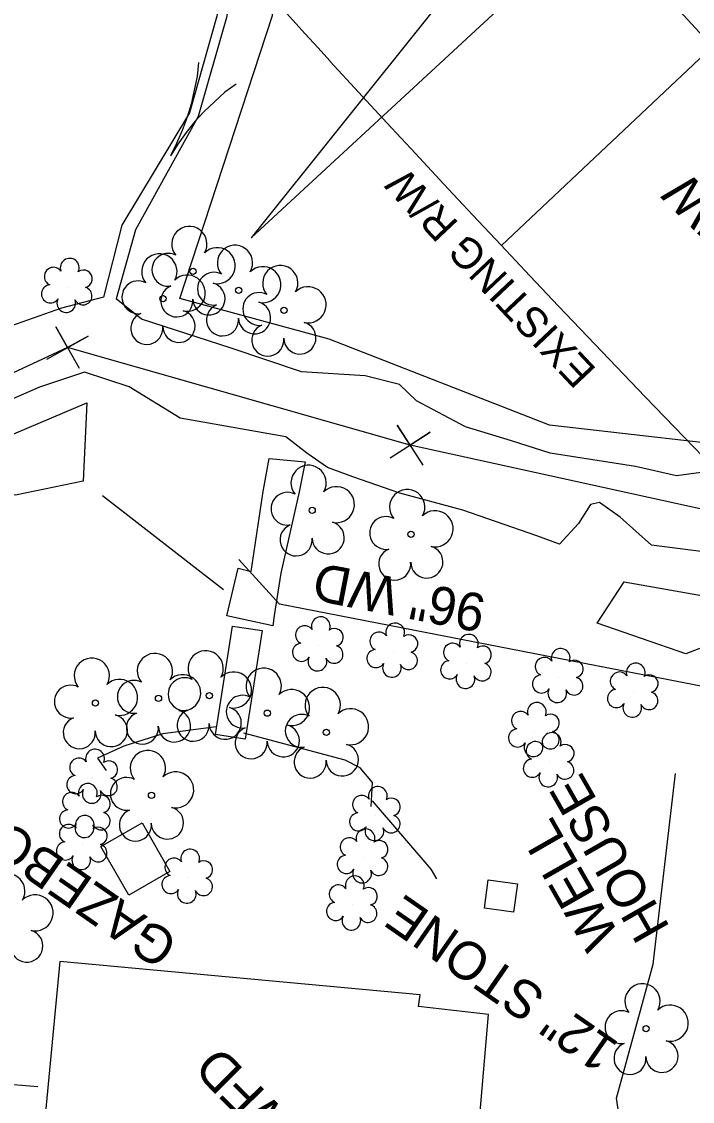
# Model space of a CAD drawing. Extents: x 472260 to 482161, y 489063 to 507124.
# Drawn here: x 478879.6 to 478950.3, y 493938.2 to 494051.9 of the extents above; entities that cross this region are included whole.
import ezdxf

# ---------------------------------------------------------------- set-up
doc = ezdxf.new("R2010")
doc.units = 0
for name, color, linetype in [('Exist Plan Preparation Watershed Blue', 7, 'Continuous'), ('Exist Roads EOP Other Cogo Point CELL', 7, 'Continuous'), ('Exist Structure Minor Drop Inlet Cogo Elevation', 7, 'Continuous'), ('Exist Structure Minor Drop Inlet Cogo Number', 7, 'Continuous'), ('Exist Structure Minor Pipes CMP 15 Inch Cogo Comment', 7, 'Continuous'), ('Exist Structure Minor Pipes CMP 15 Inch Cogo Elevation', 7, 'Continuous'), ('Exist Structure Minor Pipes CMP 15 Inch Cogo Point CELL', 7, 'Continuous'), ('Exist Structure Minor Pipes CMP 30 Inch', 7, 'Continuous'), ('Exist Utilities Water Meter CELL', 7, 'Continuous'), ('Prop Drainage Structure Drop Inlet Grate 2 Narrow Slots and Flat Grates 840 29 CELL', 7, 'Continuous'), ('Prop Drainage Structure Drop Inlet Grate 2 Wide Slots and Flat Grates 840 20 Label', 7, 'Continuous'), ('Prop Drainage Structure Outlet Berm Ditch 850 10 CELL', 7, 'Continuous'), ('Prop Drainage Structure Outlet Berm Ditch 850 10 Label', 7, 'Continuous'), ('Prop Drainage Structure Pipe RCP 24in Class III', 7, 'Continuous'), ('Prop Drainage Structure Pipe RCP 72in Class III', 7, 'Continuous'), ('Prop Drainage Structure Pipe Side Drain 18in Label', 7, 'Continuous'), ('Prop Drainage Structure Tops and Inverts LABEL', 7, 'Continuous'), ('Prop Erosion Rip Rap Pad at Outlet CELL', 7, 'Continuous'), ('Prop SS Fill Line', 7, 'Continuous'), ('Scratch_Level_7', 7, 'Continuous'), ('Scratch_Level_8', 7, 'Continuous')]:
    doc.layers.add(name, color=color, linetype=linetype)

msp = doc.modelspace()

# ---------------------------------------------------------------- linework, layer by layer
at = {"layer": 'Exist Plan Preparation Watershed Blue'}
msp.add_lwpolyline([(478901.24, 493989.35), (478902.43, 493994.36), (478903.79, 493994), (478905.06, 494002.44), (478905.69, 494005.92), (478909.5, 494005.56), (478908.87, 494002.4), (478906.92, 493993.82), (478906.21, 493989.37), (478906.07, 493988.3), (478901.24, 493989.35)], dxfattribs=at)
msp.add_lwpolyline([(478904.96, 493987.8), (478903.16, 493976.36), (478900.03, 493976.83), (478901.83, 493988.27)], close=True, dxfattribs=at)
at = {"layer": 'Exist Roads EOP Other Cogo Point CELL'}
for p, q in [((478884.44, 494017.59), (478884.44, 494017.59)), ((478920.54, 494007.33), (478920.54, 494007.33))]:
    msp.add_line(p, q, dxfattribs=at)
for points in [[(478882.25, 494016.37), (478886.62, 494018.81), (478884.44, 494017.59), (478883.22, 494019.77), (478885.65, 494015.41)], [(478918.44, 494005.98), (478922.65, 494008.67), (478920.54, 494007.33), (478919.2, 494009.43), (478921.89, 494005.22)]]:
    msp.add_lwpolyline(points, dxfattribs=at)
at = {"layer": 'Exist Structure Minor Drop Inlet Cogo Elevation'}
for centre, radius, start, end in [((480724.65, 495711.31), 2460.21, 219.63873, 222.54643), ((480415.92, 495427.95), 2041.17, 222.54643, 230.46528)]:
    msp.add_arc(centre, radius, start, end, dxfattribs=at)
at = {"layer": 'Exist Structure Minor Drop Inlet Cogo Number'}
for p, q in [((478884.44, 494017.59), (478874.79, 494013.14)), ((478920.54, 494007.33), (478884.44, 494017.59)), ((478958.36, 493999.01), (478920.54, 494007.33))]:
    msp.add_line(p, q, dxfattribs=at)
at = {"layer": 'Exist Structure Minor Pipes CMP 15 Inch Cogo Comment'}
msp.add_line((478930.18, 494028.34), (478966.81, 494062.85), dxfattribs=at)
at = {"layer": 'Exist Structure Minor Pipes CMP 15 Inch Cogo Elevation'}
msp.add_lwpolyline([(478922.85, 494052.91), (478903.78, 494029.16), (479097.91, 494208.4), (479078.84, 494184.65)], dxfattribs=at)
at = {"layer": 'Exist Utilities Water Meter CELL'}
msp.add_lwpolyline([(478944.73, 493922.51), (478942.31, 493938.56), (478946.19, 493952.67), (478948.54, 493972.74)], dxfattribs=at)
at = {"layer": 'Prop Drainage Structure Drop Inlet Grate 2 Narrow Slots and Flat Grates 840 29 CELL'}
msp.add_lwpolyline([(478916.56, 493969.87), (478922.73, 493962.68), (478923.32, 493961.64)], dxfattribs=at)
at = {"layer": 'Prop Drainage Structure Drop Inlet Grate 2 Wide Slots and Flat Grates 840 20 Label'}
for p, q in [((478897.67, 494025.63), (478897.67, 494025.63)), ((478902.48, 494023.63), (478902.48, 494023.63)), ((478894.51, 494022.74), (478894.51, 494022.74)), ((478907.25, 494021.51), (478907.25, 494021.51)), ((478910.23, 494000.46), (478910.23, 494000.46)), ((478920.64, 493997.92), (478920.64, 493997.92)), ((478887.38, 493980.16), (478887.38, 493980.16)), ((478894.03, 493980.65), (478894.03, 493980.65)), ((478899.39, 493980.94), (478899.39, 493980.94)), ((478905.51, 493979.09), (478905.51, 493979.09)), ((478911.73, 493977.07), (478911.73, 493977.07)), ((478893.29, 493970.43), (478893.29, 493970.43)), ((478945.43, 493945.86), (478945.43, 493945.86))]:
    msp.add_line(p, q, dxfattribs=at)
for centre in [(478897.67, 494025.63), (478902.48, 494023.63), (478894.51, 494022.74), (478907.25, 494021.51), (478910.23, 494000.46), (478920.64, 493997.92), (478899.39, 493980.94), (478887.38, 493980.16), (478894.03, 493980.65), (478905.51, 493979.09), (478911.73, 493977.07), (478893.29, 493970.43), (478945.43, 493945.86)]:
    msp.add_circle(centre, 0.326, dxfattribs=at)
for centre, radius, start, end in [((478897.28, 494028.5), 1.86, 330.1651, 219.7134), ((478900.22, 494026.22), 1.9, 257.1011, 134.1999), ((478902.09, 494026.51), 1.86, 330.1651, 219.7134), ((478894.12, 494025.61), 1.86, 330.1651, 219.7134), ((478895.06, 494025.78), 1.73, 62.6636, 279.3457), ((478899.87, 494023.79), 1.73, 62.6636, 279.3457), ((478905.03, 494024.22), 1.9, 257.1011, 134.1999), ((478906.87, 494024.38), 1.86, 330.1651, 219.7134), ((478891.9, 494022.89), 1.73, 62.6636, 279.3457), ((478897.06, 494023.33), 1.9, 257.1011, 134.1999), ((478899.34, 494022.73), 1.7, 181.2822, 74.56), ((478895.96, 494022.51), 1.69, 111.5671, 6.231), ((478904.65, 494021.66), 1.73, 62.6636, 279.3457), ((478909.8, 494022.1), 1.9, 257.1011, 134.1999), ((478900.77, 494020.51), 1.69, 111.5671, 6.231), ((478904.15, 494020.74), 1.7, 181.2822, 74.56), ((478892.8, 494019.62), 1.69, 111.5671, 6.231), ((478896.18, 494019.84), 1.7, 181.2822, 74.56), ((478905.55, 494018.39), 1.69, 111.5671, 6.231), ((478908.93, 494018.61), 1.7, 181.2822, 74.56), ((478909.85, 494003.34), 1.86, 330.1651, 219.7134), ((478912.78, 494001.05), 1.9, 257.1011, 134.1999), ((478920.25, 494000.79), 1.86, 330.1651, 219.7134), ((478907.63, 494000.62), 1.73, 62.6636, 279.3457), ((478923.19, 493998.51), 1.9, 257.1011, 134.1999), ((478911.91, 493997.57), 1.7, 181.2822, 74.56), ((478918.03, 493998.07), 1.73, 62.6636, 279.3457), ((478908.53, 493997.34), 1.69, 111.5671, 6.231), ((478918.93, 493994.8), 1.69, 111.5671, 6.231), ((478922.31, 493995.02), 1.7, 181.2822, 74.56), ((478899, 493983.81), 1.86, 330.1651, 219.7134), ((478887, 493983.03), 1.86, 330.1651, 219.7134), ((478893.65, 493983.53), 1.86, 330.1651, 219.7134), ((478901.94, 493981.53), 1.9, 257.1011, 134.1999), ((478905.12, 493981.97), 1.86, 330.1651, 219.7134), ((478889.93, 493980.75), 1.9, 257.1011, 134.1999), ((478891.43, 493980.81), 1.73, 62.6636, 279.3457), ((478896.78, 493981.09), 1.73, 62.6636, 279.3457), ((478896.58, 493981.24), 1.9, 257.1011, 134.1999), ((478884.78, 493980.31), 1.73, 62.6636, 279.3457), ((478908.06, 493979.68), 1.9, 257.1011, 134.1999), ((478911.34, 493979.95), 1.86, 330.1651, 219.7134), ((478902.9, 493979.25), 1.73, 62.6636, 279.3457), ((478889.05, 493977.26), 1.7, 181.2822, 74.56), ((478892.33, 493977.53), 1.69, 111.5671, 6.231), ((478895.71, 493977.75), 1.7, 181.2822, 74.56), ((478897.68, 493977.82), 1.69, 111.5671, 6.231), ((478901.06, 493978.04), 1.7, 181.2822, 74.56), ((478909.12, 493977.23), 1.73, 62.6636, 279.3457), ((478914.28, 493977.66), 1.9, 257.1011, 134.1999), ((478885.68, 493977.04), 1.69, 111.5671, 6.231), ((478907.18, 493976.19), 1.7, 181.2822, 74.56), ((478903.8, 493975.97), 1.69, 111.5671, 6.231), ((478910.02, 493973.95), 1.69, 111.5671, 6.231), ((478913.4, 493974.17), 1.7, 181.2822, 74.56), ((478892.91, 493973.31), 1.86, 330.1651, 219.7134), ((478890.69, 493970.59), 1.73, 62.6636, 279.3457), ((478895.84, 493971.02), 1.9, 257.1011, 134.1999), ((478891.59, 493967.31), 1.69, 111.5671, 6.231), ((478894.97, 493967.53), 1.7, 181.2822, 74.56), ((478878.09, 493960.34), 1.86, 330.1651, 219.7134), ((478881.02, 493958.06), 1.9, 257.1011, 134.1999), ((478880.14, 493954.57), 1.7, 181.2822, 74.56), ((478945.05, 493948.74), 1.86, 330.1651, 219.7134), ((478947.98, 493946.45), 1.9, 257.1011, 134.1999), ((478942.83, 493946.02), 1.73, 62.6636, 279.3457), ((478943.73, 493942.74), 1.69, 111.5671, 6.231), ((478947.1, 493942.96), 1.7, 181.2822, 74.56)]:
    msp.add_arc(centre, radius, start, end, dxfattribs=at)
at = {"layer": 'Prop Drainage Structure Pipe RCP 24in Class III'}
for points in [[(478900.38, 494072.2), (478902.14, 494062.49), (478900.19, 494052.51), (478897.28, 494042.33), (478890.17, 494030.48), (478888.23, 494022.9)], [(478901.38, 494072.23), (478903.07, 494062.35), (478901.18, 494052.35), (478898.21, 494041.94), (478891.61, 494030.01), (478889.57, 494022.72)], [(478888.23, 494022.9), (478883.82, 494021.74), (478876.61, 494019.2), (478872.12, 494019.62), (478867.85, 494020.05), (478854.23, 494021.26), (478853.03, 494021.3), (478852.03, 494022.25), (478851.35, 494022.91), (478845.92, 494022.26), (478843.44, 494022.29), (478841.41, 494022.16), (478839.27, 494023.06), (478827.84, 494024.22), (478820.58, 494025.15), (478816.75, 494026.12), (478813.74, 494026.36), (478811.2, 494026.83), (478808.11, 494026.57), (478805.31, 494027.01), (478802.8, 494028.13), (478794.61, 494031.02)], [(478988.66, 494005.58), (478987.8, 494005.24), (478983.59, 494006.81), (478981.37, 494005.58), (478976.65, 494005.24), (478972.46, 494005.78), (478967.01, 494005.86), (478965.68, 494006.23), (478964.23, 494006.09), (478961.45, 494003.26), (478958.39, 494003.3), (478951.24, 494004.44), (478948.65, 494004.1), (478944.3, 494005.08), (478935.33, 494006.49), (478931.24, 494007.76), (478926.39, 494009.26), (478921.23, 494011.98), (478919.42, 494013.72), (478915.83, 494014.61), (478909.09, 494015.04), (478901.7, 494017.52), (478892.25, 494020.6), (478889.57, 494022.72)], [(478952.04, 493996), (478945.99, 493996.79), (478942.71, 493999.74), (478940.52, 494001.28), (478939.57, 494001.08), (478938.29, 493999.05), (478936.3, 493996.9), (478933.9, 493997.78), (478926.11, 494000.46), (478919.47, 494002.26), (478914.51, 494003.99), (478911.84, 494004.95), (478909.65, 494006.48), (478907.44, 494008.18), (478896.32, 494010.17), (478890.95, 494013.45), (478886.22, 494015), (478881.47, 494013.44), (478875.25, 494010.73)]]:
    msp.add_lwpolyline(points, dxfattribs=at)
at = {"layer": 'Prop Drainage Structure Pipe RCP 72in Class III'}
msp.add_line((478900.89, 493992.08), (478888.13, 494001.98), dxfattribs=at)
msp.add_lwpolyline([(478975.72, 493968.99), (478962.89, 493977.98), (478955.55, 493981.1), (478906.78, 493990.56)], dxfattribs=at)
at = {"layer": 'Prop Drainage Structure Pipe Side Drain 18in Label'}
msp.add_line((478906.78, 493990.56), (478902.49, 493995.28), dxfattribs=at)
at = {"layer": 'Prop Drainage Structure Tops and Inverts LABEL'}
for points in [[(478845.51, 494172.66), (478883.99, 494125.4), (478918.58, 494086.08), (478977.87, 494021.65), (478972.39, 494009.31), (478959.23, 494006.7), (478935.26, 494009.43), (478912.01, 494018.49), (478896.29, 494022.75), (478906.04, 494052.55), (478906.48, 494061.88), (478899.05, 494070.85), (478890.35, 494076.64), (478878.48, 494092.19)], [(478830.45, 494006.7), (478843.31, 494009.15), (478852.93, 494008.27), (478876.43, 494007.53), (478886.49, 494011.79), (478886.1, 494003.54), (478878.97, 494002.05), (478855.39, 494003.66), (478841.65, 494004.49), (478824.49, 493997.99)], [(478943.11, 493992.92), (478996.29, 493983.55), (479004.31, 493971.12), (479021.82, 493961.58), (479026.76, 493948.38), (479017.52, 493939.98), (478971.78, 493979.49), (478954.8, 493987.35), (478949.6, 493985.35), (478940.27, 493988.57), (478943.11, 493992.92)]]:
    msp.add_lwpolyline(points, dxfattribs=at)
at = {"layer": 'Prop Erosion Rip Rap Pad at Outlet CELL'}
for p, q in [((478884.44, 494023.96), (478884.44, 494023.96)), ((478910.91, 493986.21), (478910.91, 493986.21)), ((478918.75, 493985.55), (478918.75, 493985.55)), ((478926.52, 493984.36), (478926.52, 493984.36)), ((478936.2, 493982.87), (478936.2, 493982.87)), ((478944.1, 493981.33), (478944.1, 493981.33)), ((478933.68, 493977.19), (478933.68, 493977.19)), ((478935.24, 493974.01), (478935.24, 493974.01)), ((478887.11, 493972.27), (478887.11, 493972.27)), ((478886.35, 493968.66), (478886.35, 493968.66)), ((478916.92, 493968.34), (478916.92, 493968.34)), ((478886.02, 493965.29), (478886.02, 493965.29)), ((478915.62, 493963.87), (478915.62, 493963.87)), ((478897.14, 493961.74), (478897.14, 493961.74)), ((478914.49, 493958.92), (478914.49, 493958.92))]:
    msp.add_line(p, q, dxfattribs=at)
for centre, radius, start, end in [((478884.67, 494026), 0.99, 334.8391, 200.4717), ((478882.96, 494025.08), 0.968, 35.8908, 245.4216), ((478886.11, 494024.83), 0.929, 284.4567, 126.0861), ((478882.64, 494023.25), 0.955, 95.1099, 327.9534), ((478886.08, 494023.03), 0.937, 204.9913, 73.4601), ((478884.31, 494022.27), 0.984, 151.2797, 21.387), ((478911.14, 493988.25), 0.99, 334.8391, 200.4717), ((478909.43, 493987.33), 0.968, 35.8908, 245.4216), ((478912.58, 493987.08), 0.929, 284.4567, 126.0861), ((478918.98, 493987.59), 0.99, 334.8391, 200.4717), ((478917.27, 493986.67), 0.968, 35.8908, 245.4216), ((478920.43, 493986.42), 0.929, 284.4567, 126.0861), ((478926.75, 493986.4), 0.99, 334.8391, 200.4717), ((478909.11, 493985.5), 0.955, 95.1099, 327.9534), ((478912.54, 493985.28), 0.937, 204.9913, 73.4601), ((478916.95, 493984.84), 0.955, 95.1099, 327.9534), ((478925.04, 493985.49), 0.968, 35.8908, 245.4216), ((478928.19, 493985.23), 0.929, 284.4567, 126.0861), ((478936.42, 493984.91), 0.99, 334.8391, 200.4717), ((478910.78, 493984.52), 0.984, 151.2797, 21.387), ((478920.39, 493984.62), 0.937, 204.9913, 73.4601), ((478924.72, 493983.66), 0.955, 95.1099, 327.9534), ((478934.71, 493984), 0.968, 35.8908, 245.4216), ((478937.87, 493983.74), 0.929, 284.4567, 126.0861), ((478918.63, 493983.86), 0.984, 151.2797, 21.387), ((478928.16, 493983.43), 0.937, 204.9913, 73.4601), ((478942.62, 493982.46), 0.968, 35.8908, 245.4216), ((478944.33, 493983.37), 0.99, 334.8391, 200.4717), ((478926.39, 493982.68), 0.984, 151.2797, 21.387), ((478934.4, 493982.17), 0.955, 95.1099, 327.9534), ((478937.83, 493981.94), 0.937, 204.9913, 73.4601), ((478945.77, 493982.2), 0.929, 284.4567, 126.0861), ((478936.07, 493981.19), 0.984, 151.2797, 21.387), ((478942.3, 493980.63), 0.955, 95.1099, 327.9534), ((478945.74, 493980.4), 0.937, 204.9913, 73.4601), ((478933.91, 493979.23), 0.99, 334.8391, 200.4717), ((478943.97, 493979.65), 0.984, 151.2797, 21.387), ((478932.2, 493978.31), 0.968, 35.8908, 245.4216), ((478935.36, 493978.06), 0.929, 284.4567, 126.0861), ((478931.88, 493976.48), 0.955, 95.1099, 327.9534), ((478935.32, 493976.26), 0.937, 204.9913, 73.4601), ((478935.47, 493976.05), 0.99, 334.8391, 200.4717), ((478933.56, 493975.5), 0.984, 151.2797, 21.387), ((478933.76, 493975.13), 0.968, 35.8908, 245.4216), ((478936.91, 493974.87), 0.929, 284.4567, 126.0861), ((478885.63, 493973.39), 0.968, 35.8908, 245.4216), ((478887.34, 493974.31), 0.99, 334.8391, 200.4717), ((478933.44, 493973.3), 0.955, 95.1099, 327.9534), ((478888.79, 493973.14), 0.929, 284.4567, 126.0861), ((478936.88, 493973.08), 0.937, 204.9913, 73.4601), ((478885.31, 493971.56), 0.955, 95.1099, 327.9534), ((478888.75, 493971.34), 0.937, 204.9913, 73.4601), ((478935.11, 493972.32), 0.984, 151.2797, 21.387), ((478886.58, 493970.7), 0.99, 334.8391, 200.4717), ((478886.99, 493970.58), 0.984, 151.2797, 21.387), ((478917.15, 493970.38), 0.99, 334.8391, 200.4717), ((478884.87, 493969.78), 0.968, 35.8908, 245.4216), ((478888.03, 493969.52), 0.929, 284.4567, 126.0861), ((478915.44, 493969.47), 0.968, 35.8908, 245.4216), ((478918.59, 493969.21), 0.929, 284.4567, 126.0861), ((478884.55, 493967.95), 0.955, 95.1099, 327.9534), ((478887.99, 493967.73), 0.937, 204.9913, 73.4601), ((478915.12, 493967.64), 0.955, 95.1099, 327.9534), ((478884.54, 493966.41), 0.968, 35.8908, 245.4216), ((478886.22, 493966.97), 0.984, 151.2797, 21.387), ((478886.25, 493967.33), 0.99, 334.8391, 200.4717), ((478918.56, 493967.42), 0.937, 204.9913, 73.4601), ((478887.69, 493966.16), 0.929, 284.4567, 126.0861), ((478915.85, 493965.91), 0.99, 334.8391, 200.4717), ((478916.79, 493966.66), 0.984, 151.2797, 21.387), ((478884.22, 493964.58), 0.955, 95.1099, 327.9534), ((478887.66, 493964.36), 0.937, 204.9913, 73.4601), ((478914.14, 493965), 0.968, 35.8908, 245.4216), ((478917.29, 493964.74), 0.929, 284.4567, 126.0861), ((478885.89, 493963.6), 0.984, 151.2797, 21.387), ((478897.37, 493963.78), 0.99, 334.8391, 200.4717), ((478913.82, 493963.16), 0.955, 95.1099, 327.9534), ((478895.66, 493962.87), 0.968, 35.8908, 245.4216), ((478898.81, 493962.61), 0.929, 284.4567, 126.0861), ((478917.26, 493962.94), 0.937, 204.9913, 73.4601), ((478895.34, 493961.04), 0.955, 95.1099, 327.9534), ((478898.78, 493960.81), 0.937, 204.9913, 73.4601), ((478914.72, 493960.96), 0.99, 334.8391, 200.4717), ((478915.49, 493962.19), 0.984, 151.2797, 21.387), ((478897.01, 493960.06), 0.984, 151.2797, 21.387), ((478913, 493960.04), 0.968, 35.8908, 245.4216), ((478916.16, 493959.79), 0.929, 284.4567, 126.0861), ((478912.69, 493958.21), 0.955, 95.1099, 327.9534), ((478916.12, 493957.99), 0.937, 204.9913, 73.4601), ((478914.36, 493957.23), 0.984, 151.2797, 21.387)]:
    msp.add_arc(centre, radius, start, end, dxfattribs=at)
at = {"layer": 'Prop SS Fill Line'}
for points in [[(478900.11, 493977.65), (478894.47, 493976.93), (478890.36, 493975.62), (478887.6, 493974.34), (478888.52, 493973.05)], [(478916.45, 493969.25), (478916.57, 493971.78), (478915.28, 493973.32), (478913.69, 493974.14), (478903.02, 493976.97)]]:
    msp.add_lwpolyline(points, dxfattribs=at)
for points in [[(478892.3, 493967.55), (478895.24, 493962.42), (478890.89, 493959.93), (478887.95, 493965.06)], [(478928.39, 493958.56), (478928.79, 493961.55), (478931.87, 493961.13), (478931.46, 493958.14)], [(478880.14, 493916.4), (478918.33, 493912.63), (478919.81, 493933.97), (478927.63, 493933.43), (478928.81, 493947.37), (478921.43, 493948.19), (478921.62, 493949.44), (478883.62, 493952.94)]]:
    msp.add_lwpolyline(points, close=True, dxfattribs=at)
at = {"layer": 'Scratch_Level_7'}
msp.add_line((478881.32, 493939.75), (478803.85, 493945.7), dxfattribs=at)
at = {"layer": 'Scratch_Level_8'}
msp.add_line((478897.75, 494042.14), (478897.75, 494042.14), dxfattribs=at)
for points in [[(478898.23, 494047.61), (478898.09, 494046.15), (478897.79, 494044.69), (478897.47, 494043.24), (478897.05, 494041.86), (478896.53, 494040.47), (478895.94, 494039.1), (478895.28, 494037.79)], [(478902.21, 494045.35), (478901.03, 494044.49), (478899.92, 494043.48), (478898.84, 494042.46), (478897.87, 494041.39), (478896.94, 494040.24), (478896.07, 494039.02), (478895.28, 494037.79)]]:
    msp.add_lwpolyline(points, dxfattribs=at)

# ---------------------------------------------------------------- texts
at = {"layer": 'Exist Structure Minor Pipes CMP 15 Inch Cogo Point CELL'}
msp.add_text('EXISTING R/W', height=3.2, rotation=133.3058, dxfattribs=at).set_placement((478940.3, 494015.27))
at = {"layer": 'Exist Structure Minor Pipes CMP 30 Inch'}
msp.add_text('CONC HW', height=4, rotation=135.6, dxfattribs=at).set_placement((478968.37, 494018.01))
at = {"layer": 'Prop Drainage Structure Outlet Berm Ditch 850 10 CELL'}
for s, rotation, p in [('HOUSE', 119.7387, (478948, 493956.5)), ('WELL', 119.7387, (478942.7, 493955.67)), ('GAZEBO', 145.2516, (478896.35, 493955.26)), ('12" STONE ', 145.2516, (478942.71, 493944.28)), ('1SWFD', 134.7507, (478913.61, 493930.95))]:
    msp.add_text(s, height=4, rotation=rotation, dxfattribs=at).set_placement(p)
at = {"layer": 'Prop Drainage Structure Outlet Berm Ditch 850 10 Label'}
msp.add_text('96" WD', height=4, rotation=169.0231, dxfattribs=at).set_placement((478928.74, 493991.49))

doc.saveas('drawing.dxf')
